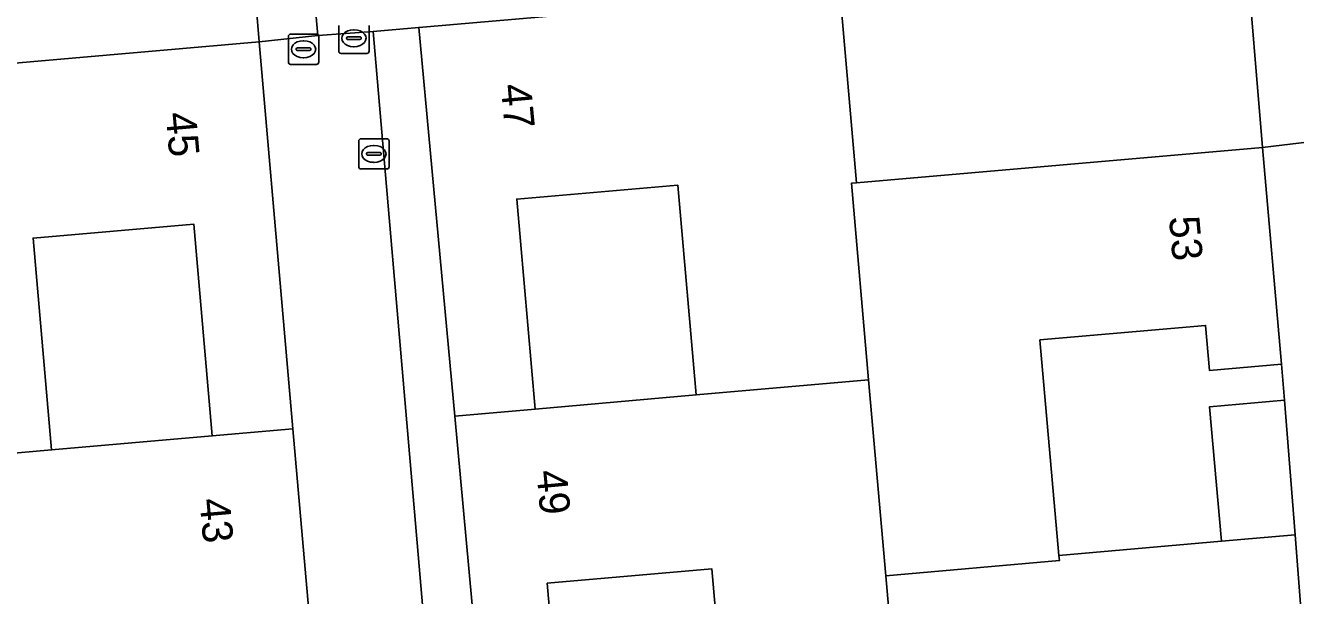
# Model space of a CAD drawing. Extents: x 162989 to 165008, y 383432 to 384338.
# Drawn here: x 164212.82 to 164254.78, y 383951.4 to 383970.26 of the extents above; entities that cross this region are included whole.
import ezdxf

# ---------------------------------------------------------------- set-up
doc = ezdxf.new("R2010")
doc.units = 0
for name, color, linetype in [('IMGEO_Brandkraan', 7, 'Continuous'), ('IMGEO_Erf', 7, 'Continuous'), ('IMGEO_Groenvoorziening', 7, 'Continuous'), ('IMGEO_Kolk', 7, 'Continuous'), ('IMGEO_Pand', 7, 'Continuous'), ('IMGEO_Pand_nummerreeks', 7, 'Continuous'), ('IMGEO_Rioolput', 7, 'Continuous'), ('IMGEO_Voetpad_halfverhard', 7, 'Continuous'), ('IMGEO_Voetpad_open', 7, 'Continuous')]:
    doc.layers.add(name, color=color, linetype=linetype)

msp = doc.modelspace()

# ---------------------------------------------------------------- linework, layer by layer
at = {"layer": 'IMGEO_Brandkraan'}
for p, q in [((164221.58, 383969.975), (164222.432, 383969.975)), ((164221.505, 383969.049), (164221.505, 383969.901)), ((164221.993, 383969.755), (164222.018, 383969.755)), ((164222.506, 383969.901), (164222.506, 383969.049)), ((164221.764, 383969.469), (164221.764, 383969.481)), ((164222.202, 383969.432), (164221.804, 383969.432)), ((164221.807, 383969.518), (164222.205, 383969.518)), ((164222.016, 383969.195), (164221.991, 383969.195)), ((164222.248, 383969.481), (164222.248, 383969.469)), ((164222.432, 383968.975), (164221.58, 383968.975))]:
    msp.add_line(p, q, dxfattribs=at)
for points in [[(164221.58, 383969.975), (164222.432, 383969.975)], [(164221.505, 383969.049), (164221.505, 383969.901)], [(164222.506, 383969.901), (164222.506, 383969.049)], [(164222.432, 383968.975), (164221.58, 383968.975)]]:
    msp.add_lwpolyline(points, dxfattribs=at)
for centre, radius, start, end in [((164221.582, 383969.899), 0.0765, 91.552, 178.448), ((164221.582, 383969.899), 0.0765, 91.552, 178.448), ((164222.43, 383969.899), 0.0765, 1.552, 88.448), ((164222.43, 383969.899), 0.0765, 1.552, 88.448), ((164221.804, 383969.478), 0.0403, 85.8775, 175.7526), ((164221.801, 383969.468), 0.0366, 178.938, 274.7102), ((164222.205, 383969.475), 0.043, 264.8664, 352.4533), ((164222.209, 383969.48), 0.0386, 1.7309, 96.639), ((164221.582, 383969.051), 0.0765, 181.552, 268.448), ((164221.582, 383969.051), 0.0765, 181.552, 268.448), ((164222.43, 383969.051), 0.0765, 271.552, 358.448), ((164222.43, 383969.051), 0.0765, 271.552, 358.448)]:
    msp.add_arc(centre, radius, start, end, dxfattribs=at)
for centre, major_axis, ratio, start_param, end_param in [((164221.992, 383969.475), (-0.387, 0.002), 0.722429, 4.712389, 7.853982), ((164222.017, 383969.475), (-0.39, 0.002), 0.717154, 1.570796, 4.712389)]:
    msp.add_ellipse(centre, major_axis=major_axis, ratio=ratio, start_param=start_param, end_param=end_param, dxfattribs=at)
at = {"layer": 'IMGEO_Erf'}
for points in [[(164225.812, 383970.195), (164224.31, 383970.064), (164226.466, 383944.948), (164228.132, 383945.102), (164227, 383957.342)], [(164234.368, 383964.984), (164229.052, 383964.518), (164229.66, 383957.575), (164234.976, 383958.04)], [(164218.376, 383963.693), (164213.068, 383963.229), (164213.681, 383956.221), (164218.989, 383956.685)], [(164254.313, 383959.063), (164251.935, 383958.855), (164251.805, 383960.338), (164246.334, 383959.859), (164246.958, 383952.731), (164252.33, 383953.202), (164251.94, 383957.651), (164254.409, 383957.867)], [(164235.489, 383952.29), (164230.056, 383951.815), (164230.675, 383944.742), (164228.665, 383944.566), (164229.244, 383938.294), (164227.099, 383938.096), (164227.105, 383937.925), (164236.601, 383938.736), (164236.121, 383945.072)]]:
    msp.add_lwpolyline(points, close=True, dxfattribs=at)
at = {"layer": 'IMGEO_Groenvoorziening'}
msp.add_lwpolyline([(164202.528, 383973.636), (164191.405, 383965.29), (164191.133, 383964.711), (164190.65, 383960.857), (164192.16, 383960.917), (164193.738, 383961.045), (164207.337, 383962.235), (164206.787, 383968.516), (164220.535, 383969.72), (164220.051, 383975.575)], dxfattribs=at)
msp.add_lwpolyline([(164253.129, 383973.007), (164222.131, 383973.745), (164222.48, 383969.929), (164224.31, 383970.064), (164225.812, 383970.195), (164239.72, 383971.412), (164240.277, 383965.055), (164253.686, 383966.227)], close=True, dxfattribs=at)
at = {"layer": 'IMGEO_Kolk'}
for p, q in [((164223.829, 383965.588), (164223.829, 383966.44)), ((164223.904, 383966.514), (164224.756, 383966.514)), ((164224.317, 383966.294), (164224.342, 383966.294)), ((164224.83, 383966.44), (164224.83, 383965.588)), ((164224.088, 383966.008), (164224.088, 383966.02)), ((164224.526, 383965.971), (164224.128, 383965.971)), ((164224.131, 383966.057), (164224.529, 383966.057)), ((164224.572, 383966.02), (164224.572, 383966.008)), ((164224.756, 383965.514), (164223.904, 383965.514)), ((164224.34, 383965.734), (164224.315, 383965.734))]:
    msp.add_line(p, q, dxfattribs=at)
for points in [[(164223.829, 383965.588), (164223.829, 383966.44)], [(164223.904, 383966.514), (164224.756, 383966.514)], [(164224.83, 383966.44), (164224.83, 383965.588)], [(164224.756, 383965.514), (164223.904, 383965.514)]]:
    msp.add_lwpolyline(points, dxfattribs=at)
for centre, radius, start, end in [((164223.906, 383966.438), 0.0765, 91.552, 178.448), ((164223.906, 383966.438), 0.0765, 91.552, 178.448), ((164224.754, 383966.438), 0.0765, 1.552, 88.448), ((164224.754, 383966.438), 0.0765, 1.552, 88.448), ((164224.128, 383966.017), 0.0403, 85.8775, 175.7526), ((164224.125, 383966.007), 0.0366, 178.938, 274.7102), ((164224.529, 383966.014), 0.043, 264.8664, 352.4533), ((164224.533, 383966.019), 0.0386, 1.7309, 96.639), ((164223.906, 383965.59), 0.0765, 181.552, 268.448), ((164223.906, 383965.59), 0.0765, 181.552, 268.448), ((164224.754, 383965.59), 0.0765, 271.552, 358.448), ((164224.754, 383965.59), 0.0765, 271.552, 358.448)]:
    msp.add_arc(centre, radius, start, end, dxfattribs=at)
for centre, major_axis, ratio, start_param, end_param in [((164224.316, 383966.014), (-0.387, 0.002), 0.722429, 4.712389, 7.853982), ((164224.341, 383966.014), (-0.39, 0.002), 0.717154, 1.570796, 4.712389)]:
    msp.add_ellipse(centre, major_axis=major_axis, ratio=ratio, start_param=start_param, end_param=end_param, dxfattribs=at)
at = {"layer": 'IMGEO_Pand'}
for points in [[(164240.277, 383965.055), (164239.72, 383971.412), (164225.812, 383970.195), (164227, 383957.342), (164229.66, 383957.575), (164229.052, 383964.518), (164234.368, 383964.984), (164234.976, 383958.04), (164240.673, 383958.539), (164240.105, 383965.04)], [(164221.656, 383956.918), (164220.535, 383969.72), (164206.787, 383968.516), (164207.337, 383962.235), (164207.975, 383955.72), (164213.681, 383956.221), (164213.068, 383963.229), (164218.376, 383963.693), (164218.989, 383956.685)], [(164240.277, 383965.055), (164240.105, 383965.04), (164240.673, 383958.539), (164241.239, 383952.057), (164246.975, 383952.561), (164246.958, 383952.731), (164246.334, 383959.859), (164251.805, 383960.338), (164251.935, 383958.855), (164254.313, 383959.063), (164253.686, 383966.227)], [(164241.621, 383945.554), (164241.805, 383945.571), (164241.239, 383952.057), (164240.673, 383958.539), (164234.976, 383958.04), (164229.66, 383957.575), (164227, 383957.342), (164228.132, 383945.102), (164228.185, 383944.524), (164228.665, 383944.566), (164230.675, 383944.742), (164230.056, 383951.815), (164235.489, 383952.29), (164236.121, 383945.072), (164236.601, 383938.736), (164242.041, 383939.221)], [(164254.766, 383953.415), (164254.409, 383957.867), (164251.94, 383957.651), (164252.33, 383953.202)], [(164214.109, 383950.481), (164219.338, 383950.939), (164219.967, 383943.752), (164222.787, 383943.999), (164221.656, 383956.918), (164218.989, 383956.685), (164213.681, 383956.221), (164207.975, 383955.72), (164208.526, 383949.431), (164209.196, 383942.696), (164212.392, 383942.976), (164214.748, 383943.182)], [(164247.308, 383946.999), (164252.667, 383947.468), (164253.29, 383940.358), (164255.754, 383940.574), (164255.591, 383942.692), (164254.766, 383953.415), (164252.33, 383953.202), (164246.958, 383952.731), (164246.975, 383952.561), (164241.239, 383952.057), (164241.805, 383945.571), (164241.621, 383945.554), (164242.041, 383939.221), (164247.936, 383939.823)]]:
    msp.add_lwpolyline(points, close=True, dxfattribs=at)
at = {"layer": 'IMGEO_Rioolput'}
for p, q in [((164223.169, 383969.412), (164223.169, 383970.264)), ((164223.657, 383970.118), (164223.682, 383970.118)), ((164224.17, 383970.264), (164224.17, 383969.412)), ((164223.428, 383969.832), (164223.428, 383969.844)), ((164223.866, 383969.795), (164223.468, 383969.795)), ((164223.471, 383969.881), (164223.869, 383969.881)), ((164223.68, 383969.558), (164223.655, 383969.558)), ((164223.912, 383969.844), (164223.912, 383969.832)), ((164224.096, 383969.338), (164223.244, 383969.338))]:
    msp.add_line(p, q, dxfattribs=at)
for points in [[(164223.169, 383969.412), (164223.169, 383970.264)], [(164224.17, 383970.264), (164224.17, 383969.412)], [(164224.096, 383969.338), (164223.244, 383969.338)]]:
    msp.add_lwpolyline(points, dxfattribs=at)
for centre, radius, start, end in [((164223.468, 383969.841), 0.0403, 85.8775, 175.7526), ((164223.465, 383969.831), 0.0366, 178.938, 274.7102), ((164223.869, 383969.838), 0.043, 264.8664, 352.4533), ((164223.873, 383969.843), 0.0386, 1.7309, 96.639), ((164223.246, 383969.414), 0.0765, 181.552, 268.448), ((164223.246, 383969.414), 0.0765, 181.552, 268.448), ((164224.094, 383969.414), 0.0765, 271.552, 358.448), ((164224.094, 383969.414), 0.0765, 271.552, 358.448)]:
    msp.add_arc(centre, radius, start, end, dxfattribs=at)
for centre, major_axis, ratio, start_param, end_param in [((164223.656, 383969.838), (-0.387, 0.002), 0.722429, 4.712389, 7.853982), ((164223.681, 383969.838), (-0.39, 0.002), 0.717154, 1.570796, 4.712389)]:
    msp.add_ellipse(centre, major_axis=major_axis, ratio=ratio, start_param=start_param, end_param=end_param, dxfattribs=at)
at = {"layer": 'IMGEO_Voetpad_halfverhard'}
for points in [[(164220.051, 383975.575), (164220.535, 383969.72), (164222.48, 383969.929), (164222.131, 383973.745)], [(164253.024, 383974.29), (164253.129, 383973.007), (164253.686, 383966.227), (164256.154, 383966.522), (164255.736, 383971.524)]]:
    msp.add_lwpolyline(points, dxfattribs=at)
at = {"layer": 'IMGEO_Voetpad_open'}
msp.add_lwpolyline([(164224.31, 383970.064), (164222.48, 383969.929), (164220.535, 383969.72), (164221.656, 383956.918), (164222.787, 383943.999), (164223.341, 383937.678), (164227.04, 383937.919), (164227.105, 383937.925), (164227.099, 383938.096), (164226.466, 383944.948)], close=True, dxfattribs=at)
msp.add_lwpolyline([(164256.154, 383966.522), (164253.686, 383966.227), (164254.313, 383959.063), (164254.409, 383957.867), (164254.766, 383953.415), (164255.591, 383942.692), (164260.052, 383943.038)], dxfattribs=at)

# ---------------------------------------------------------------- texts
at = {"layer": 'IMGEO_Pand_nummerreeks'}
for s, rotation, p in [('47', 275.2814, (164228.518, 383968.293)), ('45', 275.0038, (164217.45, 383967.36)), ('53', 275.0018, (164250.596, 383963.924)), ('49', 275.2825, (164229.698, 383955.523)), ('43', 275.0017, (164218.567, 383954.589))]:
    msp.add_text(s, height=1, rotation=rotation, dxfattribs=at).set_placement(p)

doc.saveas('drawing.dxf')
